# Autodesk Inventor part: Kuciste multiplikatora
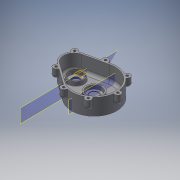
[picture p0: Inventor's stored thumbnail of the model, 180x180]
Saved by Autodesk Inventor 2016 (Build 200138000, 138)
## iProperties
Created: 2015-08
Part Number: Kuciste multiplikatora
Material: Generic
Document SubType Name: Modeling
Designer: Ugljesa
Density: 1 g/cm^3
Appearance: Default
Mass: 294.301 g
Surface Area: 1107.82 cm^2
Volume: 294.301 cm^3
Author: Ugljesa
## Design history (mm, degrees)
workplane "Work Plane1"
workplane "Work Plane2"
sketch "Sketch1"
  geometry: L1 (-49.164, -27.61)-(14.767, -73.022); L2 (-34.806, 44.019)-(41.688, 61.283); L3 (42.789, 56.405)-(-33.705, 39.141); L4 (-46.268, -23.534)-(17.663, -68.945); L5 (-33.705, 39.141)-(-33.573, -23.308); C1 r 7.5 at (-20, 5) reference; C2 r 10 at (58.199, -11.877) reference; A1 r 75 centre (58.199, -11.877) between (14.767, -73.022) and (41.688, 61.283); A2 r 70 centre (58.199, -11.877) between (17.663, -68.945) and (42.789, 56.405); A3 r 35 centre (-26, 5) between (-33.705, 39.141) and (-46.268, -23.534); A4 r 40 centre (-26, 5) between (-34.806, 44.019) and (-49.164, -27.61); 1 further point
  constraints: 10 end point, 9 point on circle, 6 centre point, 6 tangent, 1 concentric, 1 horizontal alignment, 5 other
  dimensions: "d3" = 75 radius of A1; "d6" = 5 radial gap between concentric circles of A1 A2; "d25" = 5 distance between parallel lines of L2 L3; "d105" = 5 radial gap between concentric circles of A4 A3; "d106" = 6 distance of C1.centre A3.centre; "d109" = 40 radius of A4
extrude "Extrusion11" new body sketch "Sketch1" distance "d110" = 35; taper "d111" = 0 deg; dims "d176" = 15, "d177" = 0
workplane "Work Plane7"
sketch "Sketch5"
  geometry: L1 (10.103, 51.176)-(-3.475, 46.891); L2 (-52.052, -37.533)-(-64.019, -37.533); L3 (-49.877, 49.276)-(-62.496, 49.276); L4 (132.53, -1.877)-(137.53, -1.877); L5 (132.53, -21.877)-(137.53, -21.877); L6 (132.53, -1.877)-(132.53, -21.877); C1 r 9 at (58.199, -11.877); A1 r 75 centre (58.199, -11.877) between (41.688, 61.283) and (14.767, -73.022); A2 r 10 centre (137.53, -11.877) between (137.53, -21.877) and (137.53, -1.877); 1 further point
  constraints: 12 end point, 6 point on circle, 3 centre point, 2 horizontal, 2 perpendicular, 2 tangent, 1 vertical
  dimensions: "d29" = 10 radius of A2; "d153" = 5 distance from line of L6 A2.centre
extrude "Extrusion6" join sketch "Sketch5" distance "d32" = 30; taper "d33" = 0 deg
workplane "Work Plane3"
workplane "Work Plane23"
revolve "Revolution1" stored, may be unused: angle "d79" = 90 deg
chamfer "Chamfer2" distance "d82" = 0.5; stored, may be unused: second distance "d83" = 2, angle "d84" = 45 deg
sketch "Sketch11"
  geometry: C1 r 13 at (0, 0); 1 further point
  constraints: 1 centre point
extrude "Extrusion9" cut sketch "Sketch11" distance "d85" = 39; taper "d86" = 0 deg
workplane "Work Plane4"
sketch "Sketch13"
  geometry: L1 (0, 0)-(57.224, 0) reference; L2 (4, 12.5)-(12, 12.5) reference; L3 (4, -12.5)-(12, -12.5) reference; L4 (-0.5, 14)-(0.5, 14); L5 (0.5, 14)-(0.5, 15); L6 (0.5, 15)-(-0.5, 15); L7 (0, 23.5)-(12.5, 23.5); L8 (12.5, 23.5)-(12.5, 28.5); L9 (12.5, 28.5)-(-0.5, 28.5); L10 (-0.5, 28.5)-(-0.5, 14); L11 (0, 23.5)-(0, 15); L12 (5.5, -11.5)-(5.5, 11.5) reference; L13 (0.5, -6.022)-(0.5, 39.778) reference; 1 further point
  constraints: 22 end point, 6 perpendicular, 4 horizontal, 1 collinear, 1 midpoint, 1 point on line, 1 vertical, 4 other
  dimensions: "d90" = 28 diameter of L4 L1; "d91" = 1 distance of L5.end L6.end; "d92" = 1 distance between parallel lines of L4 L6; "d93" = 47 diameter of L7 L1; "d94" = 5 distance between parallel lines of L7 L9; "d95" = 13 distance between parallel lines of L10 L8
revolve "Revolution2" sketch "Sketch13" stored, may be unused: angle "d97" = 90 deg
fillet "Fillet13" dims "d116" = 10
fillet "Fillet14" dims "d117" = 1
sketch "Sketch18"
  geometry: L1 (-14.767, -73.022)-(49.164, -27.61) reference; L2 (34.806, 44.019)-(-41.688, 61.283) reference; A1 r 40 centre (26, 5) between (49.164, -27.61) and (34.806, 44.019) reference; A2 r 75 centre (-58.199, -11.877) between (-41.688, 61.283) and (-14.767, -73.022) reference
extrude "Extrusion14" join sketch "Sketch18" distance "d122" = 5; taper "d123" = 0 deg
sketch "Sketch19"
  geometry: A1 r 10 centre (137.53, -11.877) between (137.53, -1.877) and (137.53, -21.877) reference; 1 further point
hole "Hole3" sketch "Sketch19" at (137.53, -11.877) diameter "d124" = 8; stored, may be unused: countersink angle "d128" = 90 deg, drill point angle "d130" = 120 deg; dims "d125" = 6, "d126" = 1, "d127" = 2, "d129" = 20
pattern_circular "Circular Pattern3" dims "d132" = 110 deg
pattern_circular "Circular Pattern4" dims "d135" = -55 deg
sketch "Sketch21"
  geometry: L1 (13.967, 55.026)-(33.476, 59.429); L2 (33.476, 59.429)-(32.376, 64.307); L3 (12.866, 59.904)-(13.967, 55.026); L4 (-44.927, 40.239)-(-59.621, 26.671); L5 (-59.621, 26.671)-(-63.013, 30.345); L6 (-48.319, 43.912)-(-44.927, 40.239); L7 (-26, 5)-(-55.666, 37.129); L8 (-30.413, -40.929)-(-33.308, -45.006); L9 (-46.718, -29.348)-(-30.413, -40.929); L10 (-49.614, -33.424)-(-46.718, -29.348); A1 r 10 centre (22.621, 62.105) between (32.376, 64.307) and (12.866, 59.904); A2 r 10 centre (-55.666, 37.129) between (-48.319, 43.912) and (-63.013, 30.345); A3 r 10 centre (-41.461, -39.215) between (-49.614, -33.424) and (-33.308, -45.006); 1 further point
  constraints: 20 end point, 6 point on circle, 6 tangent, 4 perpendicular, 3 centre point, 1 parallel
  dimensions: "d137" = 10 radius of A1; "d140" = 50 distance from line of L7.start L3; "d141" = 10 radius of A2; "d142" = 5 distance from line of L4 L7.end; "d145" = 10 radius of A3; "d147" = 5 distance from line of L9 A3.centre; "d148" = 3 distance from line of L7.start L10
extrude "Extrusion15" join sketch "Sketch21" distance "d149" = 30; taper "d150" = 0 deg
fillet "Fillet15" dims "d151" = 10
sketch "Sketch22"
  geometry: A1 r 10 centre (22.621, 62.105) between (32.376, 64.307) and (12.866, 59.904) reference; A2 r 10 centre (-55.666, 37.129) between (-63.013, 30.345) and (-48.319, 43.912) reference; A3 r 10 centre (-41.461, -39.215) between (-49.614, -33.424) and (-33.308, -45.006) reference; 1 further point
hole "Hole4" sketch "Sketch22" at (22.621, 62.105), (-55.666, 37.129), (-41.461, -39.215) diameter "d154" = 8; stored, may be unused: countersink angle "d158" = 90 deg, drill point angle "d160" = 120 deg; dims "d155" = 6, "d156" = 1, "d157" = 2, "d159" = 20
fillet "Fillet16" dims "d161" = 10
chamfer "Chamfer3" distance "d166" = 1; stored, may be unused: second distance "d167" = 2, angle "d168" = 45 deg
fillet "Fillet18" dims "d169" = 1
sketch "Sketch24"
  geometry: C1 r 12 at (-20, 5) reference; C2 r 13 at (-20, 5); 1 further point
  constraints: 1 centre point, 1 coincident
  dimensions: "d170" = 26 diameter of C2
extrude "Extrusion17" cut sketch "Sketch24" stored distance "d171" = 1; taper "d172" = 0 deg
fillet "Fillet19" dims "d173" = 1
body "Solid1"
sketch "Sketch10"
  geometry: L1 (-12.5, 12)-(-12.5, -6) reference; L2 (12.5, 12)-(12.5, -6) reference; L3 (-13, -29)-(-13, -35); L4 (-14, -29)-(-14, -35); L5 (-23.5, -35)-(-23.5, -15); L6 (-23.5, -15)-(-26, -15); L7 (-26, -15)-(-26, -35); L8 (0, 0)-(0, 15.071) reference; L9 (-26, -35)-(-23.5, -35); L10 (-13, -29)-(-14, -29); L11 (-13, -35)-(-14, -35); L12 (-32.61, -35)-(39.019, -35) reference; 4 further points; 1 other entity
  constraints: 22 end point, 6 vertical, 2 perpendicular, 1 collinear, 1 horizontal, 1 point on line, 9 other
  dimensions: "d73" = 26 diameter of L3 L8; "d74" = 28 diameter of L4 L8; "d77" = 47 diameter of L5 L8; "d78" = 52 diameter of L7 L8; "d174" = 6 distance of L4.start L4.end; "d175" = 20 distance of L6.end L7.end
node "Reference6"
node "Reference8"
